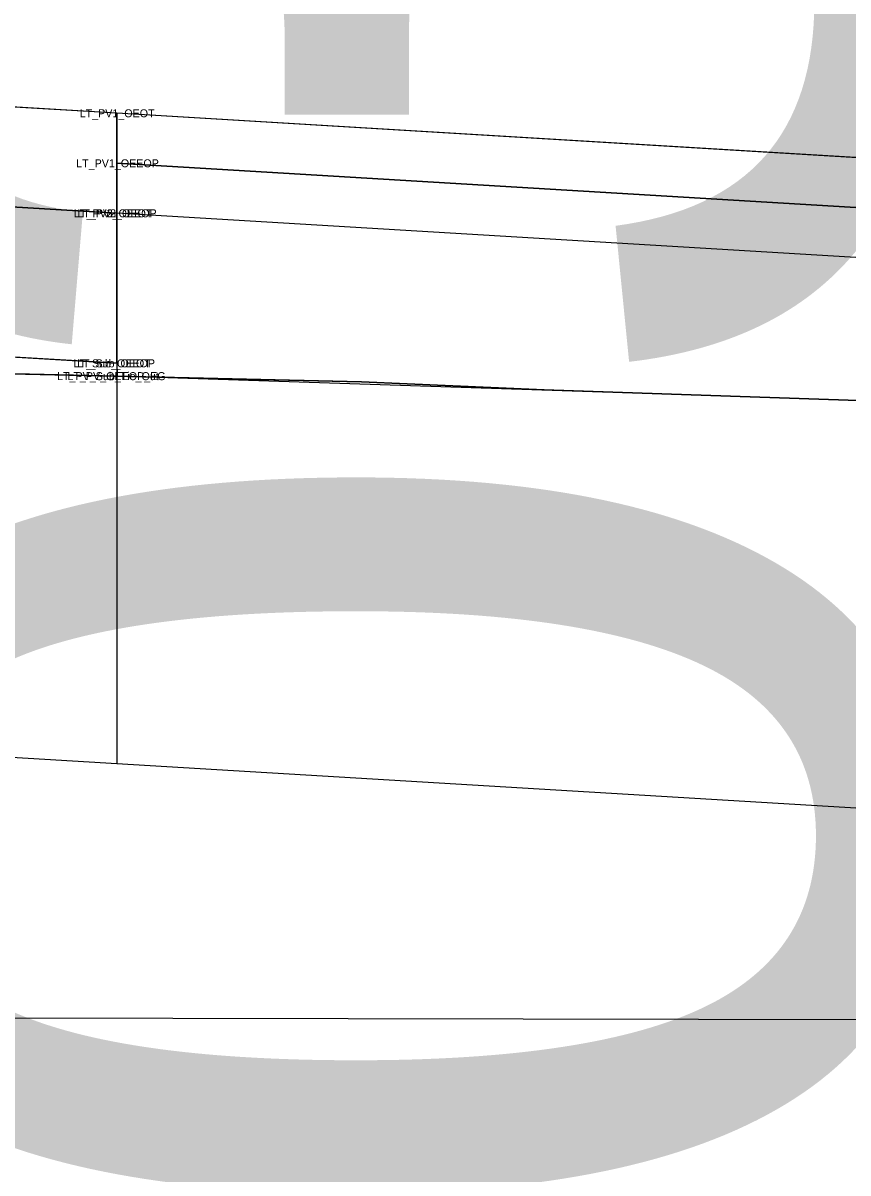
# Model space of a CAD drawing. Extents: x -516 to 303, y -10 to 5017.
# Drawn here: x 147.766 to 149.828, y 3502.271 to 3505.146 of the extents above; entities that cross this region are included whole.
import ezdxf

# ---------------------------------------------------------------- set-up
doc = ezdxf.new("R2010")
doc.units = 0
for name, color, linetype in [('Exist CMT Pavement', 7, 'Continuous'), ('Exist Cross Section Cell', 7, 'Continuous'), ('Exist XS Ground Line', 7, 'Continuous'), ('Prop CMT Pvmt Course 1', 7, 'Continuous'), ('Prop CMT Pvmt Course 1 Wedge', 7, 'Continuous'), ('Prop CMT Pvmt Course 2', 7, 'Continuous'), ('Prop CMT Pvmt Course 2 Wedge', 7, 'Continuous'), ('Prop CMT Pvmt Course 3', 7, 'Continuous'), ('Prop CMT Pvmt Course 3 Wedge', 7, 'Continuous'), ('Prop CMT Pvmt Surface', 7, 'Continuous'), ('Prop CMT Pvmt Surface Shoulder', 7, 'Continuous'), ('Prop CMT Pvmt Wedge Surface 1', 7, 'Continuous'), ('Prop CMT Pvmt Wedge Surface 2', 7, 'Continuous'), ('Prop CMT Pvmt Wedge Surface 3', 7, 'Continuous'), ('Prop CMT Shld Paved Course 1', 7, 'Continuous'), ('Prop CMT Shld Paved Course 2', 7, 'Continuous'), ('Prop CMT Shld Paved Course 3', 7, 'Continuous'), ('Prop CMT Subgrade Earthwork', 7, 'Continuous'), ('Prop Road Sect_ Material - Contact (General - Major)', 7, 'Continuous'), ('Prop Road Sect_ Misc - Drafting Aid (solid line)', 7, 'Continuous'), ('Prop Road Sect_ Recs - UC Shallow (Outline)', 7, 'Continuous'), ('Prop Road Sect_ Recs - UC Shallow (Pattern)', 7, 'Continuous'), ('Scratch_Level_0', 7, 'Continuous')]:
    doc.layers.add(name, color=color, linetype=linetype)

msp = doc.modelspace()

# ---------------------------------------------------------------- linework, layer by layer
at = {"layer": 'Exist CMT Pavement'}
msp.add_lwpolyline([(149.9985, 3504.197), (148.0015, 3504.2629)], dxfattribs=at)
at = {"layer": 'Exist XS Ground Line'}
msp.add_lwpolyline([(125.205, 3503.8945), (131.7518, 3504.2176), (136.6829, 3504.4743), (138.318, 3504.4836), (148.612, 3504.249), (149.068, 3504.2286), (150, 3504.197), (151.3235, 3504.1521), (153.2258, 3504.1006), (154.2229, 3504.0743), (155.6813, 3504.0239), (157.1104, 3503.9729), (158.1124, 3503.9391), (159.3093, 3503.9003), (160.0118, 3503.8781), (163.151, 3503.7853), (163.5861, 3503.7651), (164.5345, 3503.7181), (165.9518, 3503.6102), (166.3074, 3503.5849)], dxfattribs=at)
at = {"layer": 'Prop CMT Pvmt Course 1'}
for points in [[(150, 3504.8), (148, 3504.92)], [(148, 3504.92), (148, 3504.67), (148, 3504.67), (148, 3504.795)], [(148, 3504.795), (150, 3504.675)]]:
    msp.add_lwpolyline(points, dxfattribs=at)
at = {"layer": 'Prop CMT Pvmt Course 1 Wedge'}
msp.add_lwpolyline([(150, 3504.675), (148, 3504.795)], dxfattribs=at)
at = {"layer": 'Prop CMT Pvmt Course 2'}
msp.add_lwpolyline([(148, 3504.67), (148, 3504.67), (148, 3504.67)], close=True, dxfattribs=at)
msp.add_lwpolyline([(148, 3504.67), (148, 3504.67)], dxfattribs=at)
at = {"layer": 'Prop CMT Pvmt Course 2 Wedge'}
msp.add_lwpolyline([(150, 3504.55), (148, 3504.67)], dxfattribs=at)
at = {"layer": 'Prop CMT Pvmt Course 3'}
for points in [[(148, 3504.67), (148, 3504.67), (148, 3504.295), (148, 3504.295)], [(148, 3504.295), (148, 3504.67)]]:
    msp.add_lwpolyline(points, dxfattribs=at)
at = {"layer": 'Prop CMT Pvmt Course 3 Wedge'}
msp.add_lwpolyline([(150, 3504.55), (148, 3504.67)], dxfattribs=at)
at = {"layer": 'Prop CMT Pvmt Surface'}
msp.add_line((150, 3504.8), (148, 3504.92), dxfattribs=at)
at = {"layer": 'Prop CMT Pvmt Surface Shoulder'}
msp.add_line((148, 3504.92), (146, 3505.04), dxfattribs=at)
at = {"layer": 'Prop CMT Pvmt Wedge Surface 1'}
for points in [[(148, 3504.67), (148, 3504.92)], [(150, 3504.675), (148, 3504.795)], [(148, 3504.795), (148, 3504.67), (148, 3504.67)]]:
    msp.add_lwpolyline(points, dxfattribs=at)
at = {"layer": 'Prop CMT Pvmt Wedge Surface 2'}
for points in [[(148, 3504.67), (148, 3504.92)], [(150, 3504.55), (148, 3504.67)]]:
    msp.add_lwpolyline(points, dxfattribs=at)
at = {"layer": 'Prop CMT Pvmt Wedge Surface 3'}
for points in [[(148, 3504.67), (148, 3504.92)], [(150, 3504.55), (148, 3504.67)]]:
    msp.add_lwpolyline(points, dxfattribs=at)
at = {"layer": 'Prop CMT Shld Paved Course 1'}
for points in [[(148, 3504.92), (146, 3505.04), (145.7642, 3504.8042)], [(148, 3504.67), (148, 3504.92)], [(145.7642, 3504.8042), (148, 3504.67)]]:
    msp.add_lwpolyline(points, dxfattribs=at)
at = {"layer": 'Prop CMT Shld Paved Course 2'}
for points in [[(148, 3504.67), (145.7642, 3504.8042)], [(145.7642, 3504.8042), (148, 3504.67)], [(148, 3504.67), (148, 3504.67)]]:
    msp.add_lwpolyline(points, dxfattribs=at)
at = {"layer": 'Prop CMT Shld Paved Course 3'}
for points in [[(148, 3504.67), (145.7642, 3504.8042)], [(148, 3504.295), (148, 3504.67)], [(145.4104, 3504.4504), (148, 3504.295)]]:
    msp.add_lwpolyline(points, dxfattribs=at)
at = {"layer": 'Prop CMT Subgrade Earthwork'}
for q in [(145.4104, 3504.4504), (148.0015, 3504.2629), (148, 3504.295)]:
    msp.add_line((148, 3504.295), q, dxfattribs=at)
at = {"layer": 'Prop Road Sect_ Material - Contact (General - Major)'}
msp.add_line((176.8467, 3502.6017), (116.479, 3502.7189), dxfattribs=at)
at = {"layer": 'Prop Road Sect_ Misc - Drafting Aid (solid line)'}
msp.add_line((148, 3504.295), (148, 3503.295), dxfattribs=at)
at = {"layer": 'Prop Road Sect_ Recs - UC Shallow (Outline)'}
msp.add_lwpolyline([(165.1941, 3503.3234), (165.1941, 3503.6679), (164.5345, 3503.7181), (163.5861, 3503.7651), (163.151, 3503.7853), (159.3093, 3503.9003), (158.1124, 3503.9391), (157.1104, 3503.9729), (155.6813, 3504.0239), (154.2229, 3504.0743), (151.3235, 3504.1521), (150, 3504.197), (149.068, 3504.2286), (148.612, 3504.249), (148.0014, 3504.2629), (145.4104, 3504.322), (145.4104, 3503.4504), (148, 3503.295), (161.5292, 3502.4832), (164.1941, 3502.3234), (165.1941, 3502.3234), (165.1941, 3503.3234)], dxfattribs=at)
at = {"layer": 'Prop Road Sect_ Recs - UC Shallow (Pattern)'}
msp.add_lwpolyline([(165.1941, 3503.3234), (165.1941, 3503.6679), (164.5345, 3503.7181), (163.5861, 3503.7651), (163.151, 3503.7853), (159.3093, 3503.9003), (158.1124, 3503.9391), (157.1104, 3503.9729), (155.6813, 3504.0239), (154.2229, 3504.0743), (151.3235, 3504.1521), (150, 3504.197), (149.068, 3504.2286), (148.612, 3504.249), (148.0014, 3504.2629), (145.4104, 3504.322), (145.4104, 3503.4504), (148, 3503.295), (161.5292, 3502.4832), (164.1941, 3502.3234), (165.1941, 3502.3234), (165.1941, 3503.3234)], dxfattribs=at)

# ---------------------------------------------------------------- texts
at = {"layer": 'Exist Cross Section Cell'}
msp.add_text('N 511503.2988', height=2.8, rotation=90, dxfattribs=at).set_placement((150, 3490))
at = {"layer": 'Scratch_Level_0'}
for s, p in [('LT_PV1_OEOT', (147.9074, 3504.91)), ('LT_PV1_OEEOP', (147.8987, 3504.785)), ('LT_PV2_OEEOP', (147.8931, 3504.66)), ('LT_PV3_OEEOP', (147.8931, 3504.66)), ('LT_PV3_OEOT', (147.9017, 3504.66)), ('LT_PV2_OEOT', (147.9017, 3504.66)), ('LT_Sub_OEEOP', (147.8921, 3504.285)), ('LT_Sub_OEOT', (147.9008, 3504.285)), ('LT_PV_Sub_Tie_Out', (147.8509, 3504.2529)), ('LT_PV_OEEOP_EG', (147.8769, 3504.2529))]:
    msp.add_text(s, height=0.02, dxfattribs=at).set_placement(p)

doc.saveas('drawing.dxf')
